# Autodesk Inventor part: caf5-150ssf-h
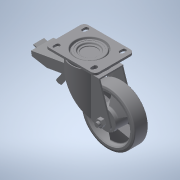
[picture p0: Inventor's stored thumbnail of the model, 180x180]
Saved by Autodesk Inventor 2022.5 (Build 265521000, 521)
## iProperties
Created: 2016-12
Part Number: caf5-150ssf-h
Material: 一般
Document SubType Name: Modeling
Designer: imaocorp
Density: 1 g/cm^3
Appearance: 既定
Author: imaocorp
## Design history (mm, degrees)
node "caf5-150ssf-h.x_t1"
node "caf5-150ssf-h"
node "Base1"
